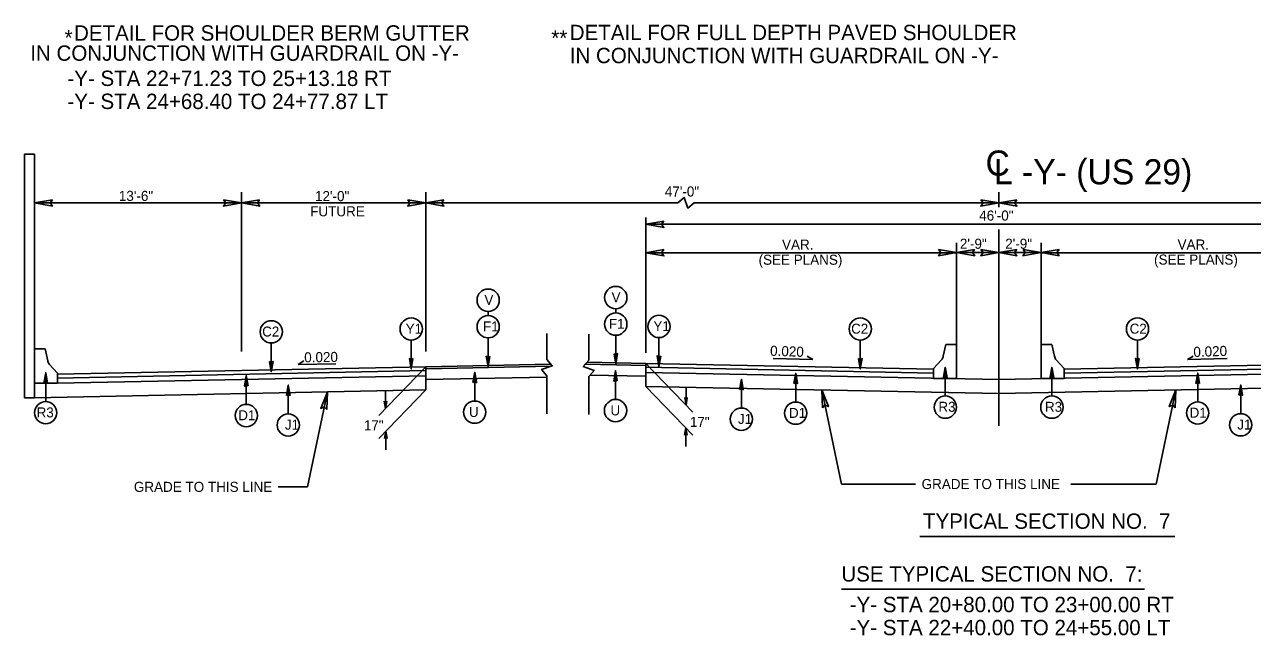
# Model space of a CAD drawing. Extents: x 1901582 to 1902252, y 193723 to 194156.
# Drawn here: x 1901984.9 to 1902064.9, y 193834.7 to 193874.4 of the extents above; entities that cross this region are included whole.
import ezdxf

# ---------------------------------------------------------------- set-up
doc = ezdxf.new("R2010")
doc.units = 0
for name, color, linetype in [('Old_Level_1', 7, 'Continuous'), ('Old_Level_11', 7, 'Continuous'), ('Old_Level_2', 7, 'Continuous'), ('Old_Level_20', 7, 'Continuous'), ('Prop Dimension', 7, 'Continuous'), ('Prop Dimension Text', 7, 'Continuous'), ('Prop Roadway Bridge', 7, 'Continuous'), ('Typical Bridge Rail CELL', 7, 'Continuous'), ('Typical Pavement Slope Information CELL', 7, 'Continuous'), ('Typical Terminator CELL', 7, 'Continuous'), ('Typical Text Asphalt at Bridge Approach CELL', 7, 'Continuous'), ('Typical Text Centerline CELL', 7, 'Continuous')]:
    doc.layers.add(name, color=color, linetype=linetype)

msp = doc.modelspace()

# ---------------------------------------------------------------- linework, layer by layer
at = {"layer": 'Old_Level_1'}
for p, q in [((1902011.021, 193852.15), (1901987.021, 193851.67)), ((1902011.021, 193851.9), (1901987.021, 193851.42)), ((1902011.021, 193852.15), (1902007.953, 193848.98)), ((1902011.021, 193852.15), (1902019.178, 193852.313)), ((1902011.021, 193852.024), (1902019.194, 193852.188)), ((1902011.021, 193852.15), (1902011.021, 193850.65)), ((1902025.36, 193852.245), (1902021.427, 193852.324)), ((1902025.36, 193852.371), (1902021.533, 193852.448)), ((1902025.36, 193852.371), (1902025.36, 193850.871)), ((1902025.36, 193852.371), (1902044.11, 193851.996)), ((1902025.36, 193852.371), (1902028.428, 193849.202)), ((1902025.36, 193852.121), (1902044.11, 193851.746)), ((1902025.36, 193851.788), (1902048.36, 193851.328)), ((1902071.36, 193851.788), (1902048.36, 193851.328)), ((1902071.36, 193852.371), (1902052.61, 193851.996)), ((1902071.36, 193852.121), (1902052.61, 193851.746)), ((1902011.021, 193851.567), (1901987.021, 193851.087)), ((1902025.36, 193851.538), (1902021.718, 193851.611)), ((1902011.021, 193850.65), (1901985.521, 193850.14)), ((1902004.613, 193850.522), (1902003.316, 193844.323)), ((1902011.021, 193850.65), (1902007.953, 193847.48)), ((1902008.402, 193850.532), (1902008.402, 193849.444)), ((1902025.36, 193850.871), (1902028.428, 193847.701)), ((1902025.36, 193850.871), (1902048.36, 193850.411)), ((1902027.979, 193850.754), (1902027.979, 193849.665)), ((1902036.825, 193850.642), (1902038.109, 193844.507)), ((1902071.36, 193850.871), (1902048.36, 193850.411)), ((1902059.895, 193850.642), (1902058.612, 193844.507)), ((1902008.402, 193849.444), (1902008.318, 193849.921)), ((1902008.402, 193849.444), (1902008.33, 193849.912)), ((1902008.342, 193849.903), (1902008.402, 193849.444)), ((1902008.402, 193849.444), (1902008.354, 193849.895)), ((1902008.366, 193849.886), (1902008.402, 193849.444)), ((1902008.402, 193849.444), (1902008.378, 193849.877)), ((1902008.39, 193849.868), (1902008.402, 193849.444)), ((1902008.402, 193849.444), (1902008.487, 193849.921)), ((1902008.475, 193849.912), (1902008.402, 193849.444)), ((1902008.402, 193849.444), (1902008.462, 193849.903)), ((1902008.45, 193849.895), (1902008.402, 193849.444)), ((1902008.402, 193849.444), (1902008.438, 193849.886)), ((1902008.426, 193849.877), (1902008.402, 193849.444)), ((1902008.402, 193849.444), (1902008.414, 193849.868)), ((1902008.402, 193849.859), (1902008.402, 193849.444)), ((1902027.979, 193849.665), (1902027.895, 193850.142)), ((1902027.906, 193850.133), (1902027.979, 193849.665)), ((1902027.979, 193849.665), (1902027.92, 193850.124)), ((1902027.932, 193850.116), (1902027.979, 193849.665)), ((1902027.979, 193849.665), (1902027.944, 193850.107)), ((1902027.955, 193850.098), (1902027.979, 193849.665)), ((1902027.979, 193849.665), (1902027.967, 193850.089)), ((1902027.979, 193849.665), (1902028.063, 193850.142)), ((1902027.979, 193849.665), (1902028.052, 193850.133)), ((1902028.04, 193850.124), (1902027.979, 193849.665)), ((1902027.979, 193849.665), (1902028.028, 193850.116)), ((1902028.015, 193850.107), (1902027.979, 193849.665)), ((1902027.979, 193849.665), (1902028.003, 193850.098)), ((1902027.991, 193850.089), (1902027.979, 193849.665)), ((1902027.979, 193850.08), (1902027.979, 193849.665)), ((1902008.419, 193847.961), (1902008.335, 193847.484)), ((1902008.346, 193847.493), (1902008.419, 193847.961)), ((1902008.419, 193847.961), (1902008.358, 193847.502)), ((1902008.37, 193847.511), (1902008.419, 193847.961)), ((1902008.419, 193847.961), (1902008.383, 193847.519)), ((1902008.395, 193847.528), (1902008.419, 193847.961)), ((1902008.419, 193847.961), (1902008.407, 193847.537)), ((1902008.419, 193847.961), (1902008.503, 193847.484)), ((1902008.431, 193847.537), (1902008.419, 193847.961)), ((1902008.419, 193847.961), (1902008.443, 193847.528)), ((1902008.454, 193847.519), (1902008.419, 193847.961)), ((1902008.419, 193847.961), (1902008.466, 193847.511)), ((1902008.478, 193847.502), (1902008.419, 193847.961)), ((1902008.419, 193847.961), (1902008.492, 193847.493)), ((1902008.419, 193847.961), (1902008.419, 193846.736)), ((1902027.963, 193848.182), (1902027.878, 193847.705)), ((1902027.963, 193848.182), (1902027.89, 193847.714)), ((1902027.903, 193847.723), (1902027.963, 193848.182)), ((1902027.963, 193848.182), (1902027.915, 193847.732)), ((1902027.927, 193847.741), (1902027.963, 193848.182)), ((1902027.963, 193848.182), (1902027.939, 193847.749)), ((1902027.951, 193847.758), (1902027.963, 193848.182)), ((1902027.963, 193848.182), (1902028.047, 193847.705)), ((1902028.035, 193847.714), (1902027.963, 193848.182)), ((1902027.963, 193848.182), (1902028.023, 193847.723)), ((1902028.011, 193847.732), (1902027.963, 193848.182)), ((1902027.963, 193848.182), (1902027.999, 193847.741)), ((1902027.987, 193847.749), (1902027.963, 193848.182)), ((1902027.963, 193848.182), (1902027.975, 193847.758)), ((1902027.963, 193848.182), (1902027.963, 193846.957)), ((1902001.407, 193844.323), (1902003.316, 193844.323)), ((1902038.109, 193844.507), (1902042.922, 193844.507)), ((1902053.047, 193844.507), (1902058.612, 193844.507))]:
    msp.add_line(p, q, dxfattribs=at)
msp.add_lwpolyline([(1902011.021, 193851.317), (1902018.91, 193851.474)], dxfattribs=at)
at = {"layer": 'Old_Level_11'}
for p, q in [((1902048.36, 193862.538), (1902048.36, 193863.53)), ((1902048.36, 193848.303), (1902048.36, 193861.095)), ((1902023.401, 193855.935), (1902023.401, 193855.657)), ((1902015.086, 193855.762), (1902015.086, 193855.484)), ((1902023.401, 193854.206), (1902023.401, 193852.332)), ((1902000.954, 193853.704), (1902000.954, 193851.83)), ((1902010.074, 193853.888), (1902010.074, 193852.014)), ((1902015.086, 193854.034), (1902015.086, 193852.16)), ((1902026.216, 193854.054), (1902026.216, 193852.18)), ((1902039.329, 193853.891), (1902039.329, 193852.017)), ((1902057.392, 193853.891), (1902057.392, 193852.017)), ((1902014.212, 193849.923), (1902014.212, 193851.797)), ((1902023.387, 193850.025), (1902023.387, 193851.9)), ((1902044.872, 193850.249), (1902044.872, 193852.123)), ((1902051.815, 193850.249), (1902051.815, 193852.123)), ((1901986.26, 193849.884), (1901986.26, 193851.758)), ((1901999.329, 193849.701), (1901999.329, 193851.575)), ((1902031.583, 193849.463), (1902031.583, 193851.337)), ((1902035.122, 193849.854), (1902035.122, 193851.728)), ((1902061.314, 193849.869), (1902061.314, 193851.743)), ((1902002.061, 193849.085), (1902002.061, 193850.959)), ((1902064.115, 193849.094), (1902064.115, 193850.968)), ((1902043.207, 193841.105), (1902059.833, 193841.105)), ((1902038.099, 193837.67), (1902057.842, 193837.67))]:
    msp.add_line(p, q, dxfattribs=at)
for points in [[(1902010.189, 193852.686), (1902010.074, 193852.014), (1902009.954, 193852.689), (1902010.074, 193852.603)], [(1902015.202, 193852.831), (1902015.086, 193852.16), (1902014.967, 193852.835), (1902015.086, 193852.749)], [(1902023.286, 193853.004), (1902023.401, 193852.332), (1902023.521, 193853.007), (1902023.401, 193852.921)], [(1902026.331, 193852.852), (1902026.216, 193852.18), (1902026.096, 193852.855), (1902026.216, 193852.77)], [(1902039.213, 193852.688), (1902039.329, 193852.017), (1902039.448, 193852.692), (1902039.329, 193852.606)], [(1902057.507, 193852.688), (1902057.392, 193852.017), (1902057.272, 193852.692), (1902057.392, 193852.606)], [(1902000.839, 193852.502), (1902000.954, 193851.83), (1902001.074, 193852.505), (1902000.954, 193852.42)], [(1902014.097, 193851.126), (1902014.212, 193851.797), (1902014.332, 193851.122), (1902014.212, 193851.208)], [(1902023.502, 193851.228), (1902023.387, 193851.9), (1902023.267, 193851.224), (1902023.387, 193851.31)], [(1902044.756, 193851.452), (1902044.872, 193852.123), (1902044.991, 193851.448), (1902044.872, 193851.534)], [(1902051.699, 193851.452), (1902051.815, 193852.123), (1902051.934, 193851.448), (1902051.815, 193851.534)], [(1901986.375, 193851.087), (1901986.26, 193851.758), (1901986.14, 193851.083), (1901986.26, 193851.169)], [(1901999.445, 193850.903), (1901999.329, 193851.575), (1901999.21, 193850.9), (1901999.329, 193850.985)], [(1902031.468, 193850.665), (1902031.583, 193851.337), (1902031.703, 193850.662), (1902031.583, 193850.747)], [(1902035.006, 193851.056), (1902035.122, 193851.728), (1902035.241, 193851.053), (1902035.122, 193851.138)], [(1902061.43, 193851.072), (1902061.314, 193851.743), (1902061.195, 193851.068), (1902061.314, 193851.154)], [(1902001.946, 193850.288), (1902002.061, 193850.959), (1902002.181, 193850.284), (1902002.061, 193850.37)], [(1902063.999, 193850.297), (1902064.115, 193850.968), (1902064.234, 193850.293), (1902064.115, 193850.379)]]:
    msp.add_lwpolyline(points, close=True, dxfattribs=at)
for centre in [(1902023.401, 193856.66), (1902015.086, 193856.487), (1902000.954, 193854.43), (1902010.074, 193854.613), (1902015.086, 193854.759), (1902023.401, 193854.931), (1902026.216, 193854.78), (1902039.329, 193854.616), (1902057.392, 193854.616), (1902044.872, 193849.524), (1902051.815, 193849.524), (1901986.26, 193849.159), (1901999.329, 193848.976), (1902014.212, 193849.198), (1902023.387, 193849.3), (1902031.583, 193848.737), (1902035.122, 193849.129), (1902061.314, 193849.144), (1902002.061, 193848.36), (1902064.115, 193848.369)]:
    msp.add_circle(centre, 0.725, dxfattribs=at)
at = {"layer": 'Prop Dimension'}
for p, q in [((1901999.021, 193853.142), (1901999.021, 193863.53)), ((1902011.021, 193853.142), (1902011.021, 193863.53)), ((1901999.021, 193862.825), (1901985.521, 193862.825)), ((1902011.021, 193862.825), (1901999.021, 193862.825)), ((1902025.36, 193853.064), (1902025.36, 193861.864)), ((1902071.36, 193861.432), (1902025.36, 193861.432)), ((1902045.61, 193853.063), (1902045.61, 193860.216)), ((1902051.11, 193853.063), (1902051.11, 193860.216)), ((1902045.61, 193859.581), (1902025.36, 193859.581)), ((1902048.36, 193859.588), (1902045.61, 193859.588)), ((1902048.36, 193859.588), (1902051.11, 193859.588)), ((1902051.11, 193859.581), (1902071.36, 193859.581))]:
    msp.add_line(p, q, dxfattribs=at)
for points in [[(1902048.36, 193862.826), (1902028.498, 193862.826), (1902028.101, 193862.485), (1902027.859, 193863.182), (1902027.446, 193862.827), (1902011.021, 193862.826)], [(1902048.36, 193862.826), (1902068.573, 193862.826), (1902068.97, 193862.485), (1902069.212, 193863.182), (1902069.625, 193862.827), (1902086.05, 193862.826)]]:
    msp.add_lwpolyline(points, dxfattribs=at)
at = {"layer": 'Prop Roadway Bridge'}
for p, q in [((1901984.881, 193850.14), (1901984.881, 193865.994)), ((1901985.521, 193865.994), (1901984.881, 193865.994)), ((1901985.521, 193850.14), (1901985.521, 193865.994)), ((1901985.521, 193850.14), (1901984.881, 193850.14))]:
    msp.add_line(p, q, dxfattribs=at)
at = {"layer": 'Typical Bridge Rail CELL'}
for p, q in [((1902044.741, 193852.834), (1902044.906, 193853.608)), ((1902044.906, 193853.608), (1902045.584, 193853.608)), ((1902045.584, 193853.608), (1902045.61, 193853.582)), ((1902045.61, 193853.582), (1902045.61, 193851.383)), ((1902051.136, 193853.608), (1902051.11, 193853.582)), ((1902051.11, 193853.582), (1902051.11, 193851.383)), ((1902051.814, 193853.608), (1902051.136, 193853.608)), ((1902051.979, 193852.834), (1902051.814, 193853.608)), ((1901985.548, 193853.311), (1901985.521, 193853.285)), ((1901985.521, 193853.285), (1901985.521, 193851.087)), ((1901986.226, 193853.311), (1901985.548, 193853.311)), ((1901986.39, 193852.538), (1901986.226, 193853.311)), ((1902044.11, 193852.035), (1902044.623, 193852.602)), ((1902052.61, 193852.035), (1902052.097, 193852.602)), ((1901987.021, 193851.739), (1901986.508, 193852.306)), ((1902044.11, 193852.035), (1902044.11, 193851.383)), ((1902052.61, 193852.035), (1902052.61, 193851.383)), ((1901985.521, 193851.087), (1901987.021, 193851.087)), ((1901987.021, 193851.739), (1901987.021, 193851.087)), ((1902045.61, 193851.383), (1902044.11, 193851.383)), ((1902051.11, 193851.383), (1902052.61, 193851.383))]:
    msp.add_line(p, q, dxfattribs=at)
for centre, start, end in [((1902044.252, 193852.938), 317.86989, 348.00424), ((1902052.468, 193852.938), 191.99576, 222.13011), ((1901986.879, 193852.641), 191.99576, 222.13011)]:
    msp.add_arc(centre, 0.5, start, end, dxfattribs=at)
at = {"layer": 'Typical Pavement Slope Information CELL'}
for p, q in [((1902036.244, 193852.621), (1902033.655, 193852.682)), ((1902036.244, 193852.621), (1902035.869, 193852.849)), ((1902060.654, 193852.621), (1902061.029, 193852.849)), ((1902060.654, 193852.621), (1902063.243, 193852.682)), ((1902002.7, 193852.302), (1902003.076, 193852.529)), ((1902002.7, 193852.302), (1902005.17, 193852.352))]:
    msp.add_line(p, q, dxfattribs=at)
at = {"layer": 'Typical Terminator CELL'}
for points in [[(1901986.693, 193863.027), (1901985.521, 193862.825), (1901986.699, 193862.617), (1901986.55, 193862.825)], [(1901997.85, 193863.027), (1901999.021, 193862.825), (1901997.843, 193862.617), (1901997.993, 193862.825)], [(1902000.193, 193863.027), (1901999.021, 193862.825), (1902000.2, 193862.617), (1902000.05, 193862.825)], [(1902009.85, 193863.027), (1902011.021, 193862.825), (1902009.843, 193862.617), (1902009.993, 193862.825)], [(1902012.193, 193863.027), (1902011.021, 193862.825), (1902012.2, 193862.617), (1902012.05, 193862.825)], [(1902047.188, 193863.027), (1902048.36, 193862.825), (1902047.182, 193862.617), (1902047.332, 193862.825)], [(1902049.532, 193863.027), (1902048.36, 193862.825), (1902049.538, 193862.617), (1902049.389, 193862.825)], [(1902026.532, 193861.634), (1902025.36, 193861.432), (1902026.538, 193861.224), (1902026.389, 193861.432)], [(1902026.532, 193859.783), (1902025.36, 193859.581), (1902026.538, 193859.373), (1902026.389, 193859.581)], [(1902044.438, 193859.79), (1902045.61, 193859.588), (1902044.432, 193859.379), (1902044.582, 193859.588)], [(1902046.782, 193859.79), (1902045.61, 193859.588), (1902046.788, 193859.379), (1902046.639, 193859.588)], [(1902047.188, 193859.79), (1902048.36, 193859.588), (1902047.182, 193859.379), (1902047.332, 193859.588)], [(1902049.532, 193859.79), (1902048.36, 193859.588), (1902049.538, 193859.379), (1902049.389, 193859.588)], [(1902049.938, 193859.79), (1902051.11, 193859.588), (1902049.932, 193859.379), (1902050.082, 193859.588)], [(1902052.282, 193859.79), (1902051.11, 193859.588), (1902052.288, 193859.379), (1902052.139, 193859.588)], [(1902004.572, 193849.366), (1902004.613, 193850.522), (1902004.18, 193849.441), (1902004.408, 193849.542)], [(1902036.867, 193849.486), (1902036.825, 193850.642), (1902037.258, 193849.561), (1902037.03, 193849.662)], [(1902059.854, 193849.486), (1902059.895, 193850.642), (1902059.462, 193849.561), (1902059.69, 193849.662)]]:
    msp.add_lwpolyline(points, close=True, dxfattribs=at)
at = {"layer": 'Typical Text Asphalt at Bridge Approach CELL'}
for points in [[(1902018.91, 193849.098), (1902018.91, 193851.573), (1902018.569, 193851.97), (1902019.265, 193852.212), (1902018.91, 193852.625), (1902018.906, 193854.327)], [(1902021.641, 193849.047), (1902021.641, 193851.522), (1902021.983, 193851.919), (1902021.287, 193852.161), (1902021.641, 193852.574), (1902021.645, 193854.276)]]:
    msp.add_lwpolyline(points, dxfattribs=at)

# ---------------------------------------------------------------- texts
at = {"layer": 'Old_Level_1'}
for s, p in [('47\'-0"', (1902026.597, 193863.241)), ('13\'-6"', (1901991.025, 193862.955)), ('12\'-0"', (1902003.805, 193862.939)), ('46\'-0"', (1902047.081, 193861.673)), ('VAR.', (1902034.234, 193859.78)), ('VAR.', (1902060.004, 193859.79)), ('(SEE PLANS)', (1902032.705, 193858.796)), ('(SEE PLANS)', (1902058.474, 193858.806)), ('GRADE TO THIS LINE', (1901992.004, 193844.003)), ('GRADE TO THIS LINE', (1902043.328, 193844.187))]:
    msp.add_text(s, height=0.656, dxfattribs=at).set_placement(p)
at = {"layer": 'Old_Level_11'}
for s, p in [('DETAIL FOR SHOULDER BERM GUTTER ', (1901988.105, 193873.393)), ('DETAIL FOR FULL DEPTH PAVED SHOULDER ', (1902020.403, 193873.425)), ('*', (1901987.488, 193873.081)), ('**', (1902019.2, 193873.068)), ('IN CONJUNCTION WITH GUARDRAIL ON -Y-', (1901985.255, 193872.082)), ('IN CONJUNCTION WITH GUARDRAIL ON -Y-', (1902020.403, 193871.925)), ('-Y- STA 22+71.23 TO 25+13.18 RT', (1901987.673, 193870.439)), ('-Y- STA 24+68.40 TO 24+77.87 LT', (1901987.673, 193868.939)), ('TYPICAL SECTION NO.  7', (1902043.418, 193841.599)), ('USE TYPICAL SECTION NO.  7:', (1902038.099, 193838.164)), ('-Y- STA 20+80.00 TO 23+00.00 RT', (1902038.644, 193836.169)), ('-Y- STA 22+40.00 TO 24+55.00 LT', (1902038.644, 193834.669))]:
    msp.add_text(s, height=1, dxfattribs=at).set_placement(p)
at = {"layer": 'Old_Level_2'}
for rotation, p in [(358.02792, (1902033.448, 193852.872)), (1.97208, (1902061.046, 193852.789)), (0.79853, (1902003.107, 193852.437))]:
    msp.add_text('0.020', height=0.656, rotation=rotation, dxfattribs=at).set_placement(p)
at = {"layer": 'Old_Level_20'}
for s, height, p in [('V', 0.649, (1902014.844, 193856.181)), ('V', 0.649, (1902023.128, 193856.354)), ('F1', 0.6491, (1902014.755, 193854.453)), ('F1', 0.6491, (1902022.96, 193854.625)), ('Y1', 0.6491, (1902025.855, 193854.473)), ('C2', 0.6491, (1902000.365, 193854.123)), ('Y1', 0.6491, (1902009.713, 193854.307)), ('C2', 0.6491, (1902038.739, 193854.31)), ('C2', 0.6491, (1902056.885, 193854.31)), ('R3', 0.6491, (1901985.673, 193848.855)), ('U', 0.649, (1902013.841, 193848.883)), ('U', 0.649, (1902023.059, 193848.986)), ('D1', 0.6491, (1902034.689, 193848.825)), ('R3', 0.6491, (1902044.427, 193849.22)), ('R3', 0.6491, (1902051.37, 193849.22)), ('D1', 0.6491, (1902060.793, 193848.84)), ('D1', 0.6491, (1901998.808, 193848.672)), ('J1', 0.6491, (1902001.843, 193848.056)), ('17"', 0.6491, (1902006.997, 193848.018)), ('17"', 0.6491, (1902028.236, 193848.24)), ('J1', 0.6491, (1902031.365, 193848.434)), ('J1', 0.6491, (1902063.897, 193848.065))]:
    msp.add_text(s, height=height, dxfattribs=at).set_placement(p)
at = {"layer": 'Prop Dimension Text'}
for s, p in [('FUTURE', (1902003.491, 193861.949)), ('2\'-9"', (1902045.821, 193859.838)), ('2\'-9"', (1902048.775, 193859.838))]:
    msp.add_text(s, height=0.656, dxfattribs=at).set_placement(p)
at = {"layer": 'Typical Text Centerline CELL'}
msp.add_text('C', height=1.64, dxfattribs=at).set_placement((1902047.492, 193864.599))
msp.add_text('L -Y- (US 29)', height=1.64109, rotation=359.9469, dxfattribs=at).set_placement((1902048.037, 193864.039))

doc.saveas('drawing.dxf')
